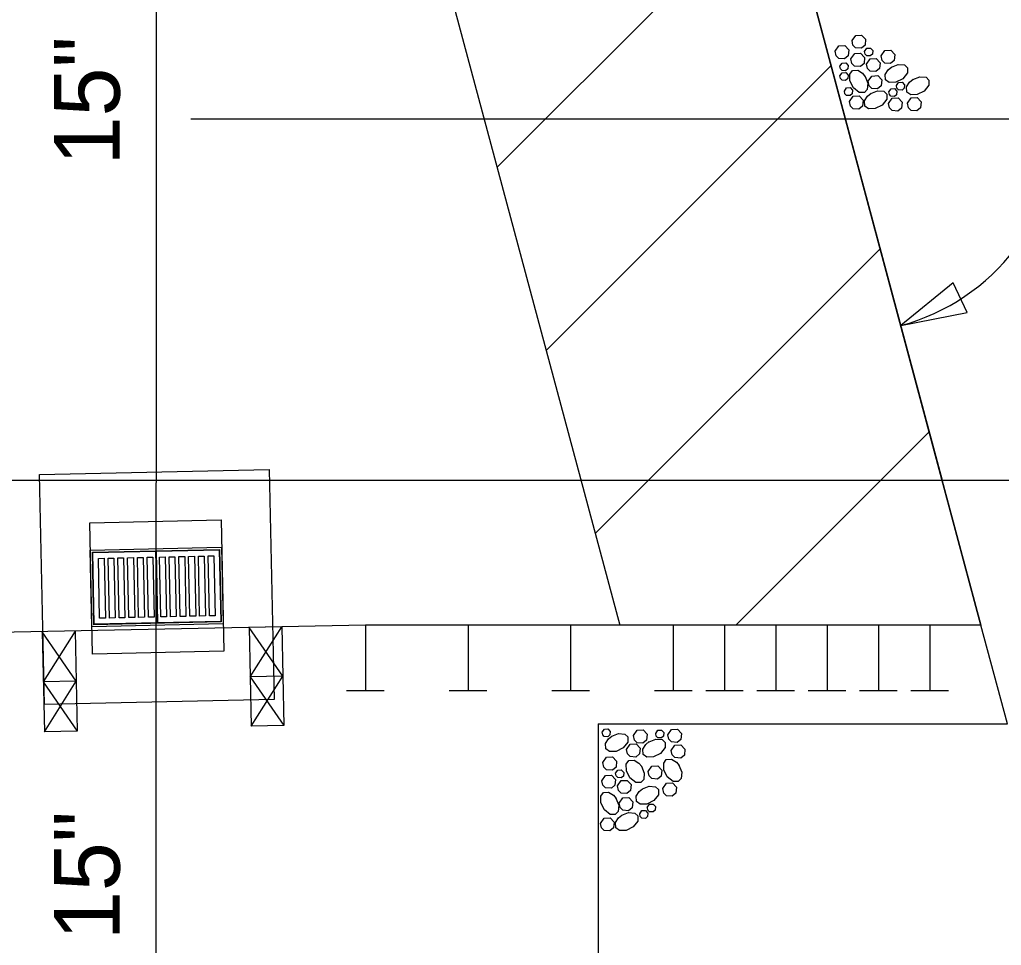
# Model space of a CAD drawing. Extents: x 471 to 2034, y -623 to 126.
# Drawn here: x 632.49 to 662.4, y -311.74 to -283.55 of the extents above; entities that cross this region are included whole.
import ezdxf

# ---------------------------------------------------------------- set-up
doc = ezdxf.new("R2010")
doc.units = 0
for name, color, linetype in [('Auto Dimensioning', 7, 'Continuous'), ('Default', 7, 'Continuous'), ('Mis Object Lines', 7, 'Continuous'), ('Miscellaneous Lines CELL', 7, 'Continuous'), ('Prop EOT', 7, 'Continuous'), ('Prop Horizontal Alignment', 7, 'Continuous'), ('Sub End Bent Cap Lines CELL', 7, 'Continuous'), ('Sup Concrete Girder Lines', 7, 'Continuous'), ('Text', 7, 'Continuous')]:
    doc.layers.add(name, color=color, linetype=linetype)

# ---------------------------------------------------------------- blocks, each defined once
blk = doc.blocks.new('AH')
at = {"layer": 'Sub End Bent Cap Lines CELL'}
blk.add_lwpolyline([(0, 0), (-1.25, 0.312), (-1.25, -0.312)], close=True, dxfattribs=at)

msp = doc.modelspace()

# ---------------------------------------------------------------- linework, layer by layer
at = {"layer": 'Auto Dimensioning'}
msp.add_arc((657.644, -286.575), 6.513, 285, 360, dxfattribs=at)
at = {"layer": 'Default'}
for p, q in [((661.775, -301.992), (653.513, -271.159)), ((654.697, -275.575), (660.592, -297.575)), ((636.644, -299.662), (636.642, -314.576)), ((636.644, -299.662), (636.644, -299.662)), ((636.669, -300.828), (636.669, -300.828)), ((638.669, -300.785), (638.669, -300.785)), ((634.67, -300.871), (634.67, -300.871)), ((643.025, -301.992), (596.283, -302.927)), ((636.694, -301.995), (636.694, -301.995)), ((643.025, -301.992), (643.025, -303.992)), ((661.775, -301.992), (643.025, -301.992)), ((646.15, -301.992), (646.15, -303.992)), ((649.275, -301.992), (649.275, -303.992)), ((652.4, -301.992), (652.4, -303.992)), ((653.963, -301.992), (653.963, -303.992)), ((655.525, -301.992), (655.525, -303.992)), ((657.088, -301.992), (657.088, -303.992)), ((658.65, -301.992), (658.65, -303.992)), ((660.213, -301.992), (660.213, -303.992)), ((633.183, -302.189), (633.244, -305.241)), ((634.213, -303.695), (633.183, -302.189)), ((634.183, -302.169), (633.213, -303.715)), ((634.183, -302.169), (634.244, -305.221)), ((640.483, -302.043), (639.483, -302.063)), ((639.483, -302.063), (639.543, -305.062)), ((639.483, -302.063), (639.513, -303.563)), ((640.513, -303.543), (639.483, -302.063)), ((639.513, -303.563), (640.483, -302.043)), ((640.483, -302.043), (640.543, -305.042)), ((634.213, -303.695), (633.213, -303.715)), ((633.213, -303.715), (634.244, -305.221)), ((633.244, -305.241), (634.213, -303.695)), ((640.513, -303.543), (639.513, -303.563)), ((639.513, -303.563), (640.543, -305.042)), ((639.543, -305.062), (640.513, -303.543)), ((643.598, -303.992), (642.452, -303.992)), ((646.723, -303.992), (645.577, -303.992)), ((649.848, -303.992), (648.702, -303.992)), ((652.973, -303.992), (651.827, -303.992)), ((654.535, -303.992), (653.39, -303.992)), ((656.098, -303.992), (654.952, -303.992)), ((657.66, -303.992), (656.515, -303.992)), ((659.223, -303.992), (658.077, -303.992)), ((660.785, -303.992), (659.64, -303.992)), ((634.244, -305.221), (633.244, -305.241)), ((640.543, -305.042), (639.543, -305.062))]:
    msp.add_line(p, q, dxfattribs=at)
for points in [[(633.095, -297.404), (640.093, -297.254), (640.243, -304.252), (633.245, -304.402)], [(634.627, -298.872), (638.626, -298.786), (638.712, -302.785), (634.712, -302.871)]]:
    msp.add_lwpolyline(points, close=True, dxfattribs=at)
for points in [[(634.645, -299.705), (638.644, -299.619), (638.694, -301.952), (634.695, -302.037), (634.645, -299.705)], [(634.708, -299.766), (638.583, -299.683), (638.63, -301.891), (634.756, -301.974), (634.708, -299.766)], [(634.719, -299.776), (636.635, -299.735), (636.682, -301.922), (634.766, -301.963), (634.719, -299.776)], [(635.186, -299.948), (635.364, -299.945), (635.403, -301.767), (635.226, -301.771), (635.186, -299.948)], [(635.483, -299.942), (635.66, -299.938), (635.699, -301.761), (635.522, -301.764), (635.483, -299.942)], [(635.78, -299.936), (635.957, -299.932), (635.996, -301.754), (635.819, -301.758), (635.78, -299.936)], [(636.077, -299.929), (636.254, -299.925), (636.293, -301.748), (636.116, -301.752), (636.077, -299.929)], [(636.374, -299.923), (636.551, -299.919), (636.59, -301.742), (636.413, -301.745), (636.374, -299.923)], [(636.656, -299.734), (638.572, -299.693), (638.619, -301.88), (636.703, -301.921), (636.656, -299.734)], [(636.749, -299.915), (636.926, -299.911), (636.965, -301.734), (636.788, -301.737), (636.749, -299.915)], [(637.045, -299.908), (637.222, -299.905), (637.261, -301.727), (637.084, -301.731), (637.045, -299.908)], [(637.342, -299.902), (637.519, -299.898), (637.558, -301.721), (637.381, -301.725), (637.342, -299.902)], [(637.639, -299.896), (637.816, -299.892), (637.855, -301.714), (637.678, -301.718), (637.639, -299.896)], [(637.936, -299.889), (638.113, -299.886), (638.152, -301.708), (637.975, -301.712), (637.936, -299.889)], [(638.232, -299.883), (638.41, -299.879), (638.449, -301.702), (638.272, -301.705), (638.232, -299.883)], [(634.89, -299.955), (635.067, -299.951), (635.106, -301.773), (634.929, -301.777), (634.89, -299.955)]]:
    msp.add_lwpolyline(points, dxfattribs=at)
at = {"layer": 'Mis Object Lines'}
for p, q in [((642.513, -271.159), (650.775, -301.992)), ((647.038, -288.046), (655.714, -279.371)), ((648.533, -293.623), (657.208, -284.948)), ((650.027, -299.2), (658.702, -290.525)), ((654.306, -301.992), (660.197, -296.101)), ((661.775, -301.992), (650.775, -301.992))]:
    msp.add_line(p, q, dxfattribs=at)
msp.add_lwpolyline([(642.513, -271.159), (653.513, -271.159), (661.775, -301.992)], dxfattribs=at)
at = {"layer": 'Miscellaneous Lines CELL'}
for points in [[(657.847, -284.191), (657.959, -284.031), (658.138, -284.021), (658.263, -284.15), (658.245, -284.331), (658.134, -284.423), (657.958, -284.41), (657.874, -284.329), (657.847, -284.191)], [(657.333, -284.512), (657.445, -284.352), (657.624, -284.342), (657.748, -284.471), (657.73, -284.652), (657.62, -284.743), (657.443, -284.731), (657.36, -284.65), (657.333, -284.512)], [(657.816, -284.744), (657.928, -284.585), (658.107, -284.575), (658.231, -284.704), (658.213, -284.884), (658.103, -284.976), (657.926, -284.963), (657.843, -284.883), (657.816, -284.744)], [(658.232, -284.517), (658.3, -284.422), (658.407, -284.416), (658.482, -284.493), (658.471, -284.601), (658.404, -284.657), (658.298, -284.649), (658.249, -284.601), (658.232, -284.517)], [(658.735, -284.655), (658.847, -284.495), (659.026, -284.485), (659.15, -284.614), (659.132, -284.795), (659.022, -284.887), (658.845, -284.874), (658.762, -284.793), (658.735, -284.655)], [(657.48, -284.968), (657.547, -284.872), (657.654, -284.866), (657.729, -284.944), (657.718, -285.052), (657.652, -285.107), (657.546, -285.099), (657.496, -285.051), (657.48, -284.968)], [(658.289, -284.903), (658.401, -284.743), (658.58, -284.733), (658.705, -284.862), (658.687, -285.043), (658.576, -285.135), (658.4, -285.122), (658.317, -285.041), (658.29, -284.903)], [(659.048, -284.996), (659.258, -284.913), (659.45, -284.93), (659.542, -285.017), (659.539, -285.173), (659.4, -285.351), (659.185, -285.458), (658.983, -285.461), (658.869, -285.38), (658.859, -285.219), (658.951, -285.075), (659.057, -284.991)], [(657.48, -285.264), (657.547, -285.168), (657.654, -285.162), (657.729, -285.239), (657.718, -285.348), (657.652, -285.403), (657.546, -285.395), (657.496, -285.347), (657.48, -285.264)], [(658.244, -285.279), (658.327, -285.489), (658.311, -285.682), (658.224, -285.773), (658.067, -285.77), (657.89, -285.631), (657.782, -285.417), (657.779, -285.214), (657.86, -285.101), (658.021, -285.09), (658.165, -285.182), (658.249, -285.288)], [(658.339, -285.427), (658.451, -285.268), (658.63, -285.257), (658.755, -285.386), (658.737, -285.567), (658.626, -285.659), (658.449, -285.646), (658.366, -285.566), (658.339, -285.427)], [(659.699, -285.371), (659.908, -285.288), (660.101, -285.304), (660.192, -285.391), (660.189, -285.547), (660.05, -285.725), (659.836, -285.832), (659.634, -285.836), (659.52, -285.755), (659.509, -285.594), (659.601, -285.45), (659.707, -285.365)], [(659.199, -285.558), (659.266, -285.462), (659.374, -285.456), (659.448, -285.533), (659.438, -285.642), (659.371, -285.697), (659.265, -285.689), (659.215, -285.641), (659.199, -285.558)], [(657.615, -285.724), (657.682, -285.629), (657.79, -285.622), (657.864, -285.7), (657.853, -285.808), (657.787, -285.863), (657.681, -285.856), (657.631, -285.807), (657.615, -285.724)], [(657.771, -286.043), (657.884, -285.884), (658.062, -285.874), (658.187, -286.003), (658.169, -286.183), (658.058, -286.275), (657.882, -286.262), (657.799, -286.182), (657.772, -286.043)], [(658.418, -285.798), (658.627, -285.714), (658.82, -285.731), (658.911, -285.818), (658.908, -285.974), (658.769, -286.152), (658.555, -286.259), (658.353, -286.263), (658.239, -286.182), (658.228, -286.021), (658.32, -285.877), (658.426, -285.792)], [(658.968, -285.752), (659.035, -285.657), (659.143, -285.65), (659.217, -285.728), (659.206, -285.836), (659.14, -285.891), (659.034, -285.884), (658.984, -285.835), (658.968, -285.752)], [(658.96, -286.102), (659.073, -285.943), (659.251, -285.933), (659.376, -286.062), (659.358, -286.242), (659.247, -286.334), (659.071, -286.322), (658.988, -286.241), (658.961, -286.102)], [(659.539, -286.096), (659.651, -285.936), (659.83, -285.926), (659.954, -286.055), (659.936, -286.236), (659.825, -286.328), (659.649, -286.315), (659.566, -286.234), (659.539, -286.096)], [(650.236, -305.248), (650.303, -305.152), (650.41, -305.146), (650.485, -305.223), (650.474, -305.332), (650.408, -305.387), (650.302, -305.379), (650.252, -305.331), (650.236, -305.248)], [(650.526, -305.371), (650.736, -305.288), (650.928, -305.304), (651.02, -305.391), (651.017, -305.547), (650.878, -305.725), (650.663, -305.832), (650.461, -305.836), (650.347, -305.755), (650.337, -305.594), (650.429, -305.45), (650.535, -305.365)], [(651.19, -305.35), (651.302, -305.191), (651.481, -305.181), (651.605, -305.31), (651.587, -305.49), (651.477, -305.582), (651.3, -305.569), (651.217, -305.489), (651.19, -305.35)], [(651.87, -305.285), (651.937, -305.189), (652.045, -305.183), (652.119, -305.26), (652.108, -305.369), (652.042, -305.424), (651.936, -305.416), (651.886, -305.368), (651.87, -305.285)], [(652.237, -305.326), (652.349, -305.167), (652.528, -305.156), (652.652, -305.285), (652.634, -305.466), (652.524, -305.558), (652.347, -305.545), (652.264, -305.465), (652.237, -305.326)], [(650.979, -305.772), (651.091, -305.612), (651.27, -305.602), (651.395, -305.731), (651.377, -305.912), (651.266, -306.004), (651.089, -305.991), (651.006, -305.91), (650.979, -305.772)], [(651.665, -305.54), (651.875, -305.457), (652.067, -305.474), (652.159, -305.561), (652.156, -305.717), (652.017, -305.894), (651.802, -306.002), (651.6, -306.005), (651.486, -305.924), (651.475, -305.763), (651.568, -305.619), (651.673, -305.535)], [(652.343, -305.803), (652.455, -305.644), (652.634, -305.634), (652.758, -305.762), (652.74, -305.943), (652.629, -306.035), (652.453, -306.022), (652.37, -305.942), (652.343, -305.803)], [(650.261, -306.172), (650.373, -306.012), (650.552, -306.002), (650.676, -306.131), (650.658, -306.312), (650.548, -306.404), (650.371, -306.391), (650.288, -306.31), (650.261, -306.172)], [(651.437, -306.284), (651.52, -306.494), (651.503, -306.686), (651.416, -306.778), (651.26, -306.775), (651.083, -306.636), (650.975, -306.422), (650.972, -306.219), (651.053, -306.105), (651.214, -306.095), (651.358, -306.187), (651.442, -306.293)], [(652.576, -306.257), (652.659, -306.467), (652.642, -306.659), (652.555, -306.751), (652.399, -306.748), (652.221, -306.609), (652.114, -306.394), (652.111, -306.192), (652.191, -306.078), (652.353, -306.067), (652.497, -306.16), (652.581, -306.266)], [(650.646, -306.498), (650.713, -306.403), (650.82, -306.397), (650.895, -306.474), (650.884, -306.582), (650.818, -306.638), (650.712, -306.63), (650.662, -306.581), (650.646, -306.498)], [(651.638, -306.443), (651.75, -306.284), (651.929, -306.273), (652.054, -306.402), (652.036, -306.583), (651.925, -306.675), (651.748, -306.662), (651.665, -306.581), (651.638, -306.443)], [(650.229, -306.725), (650.341, -306.566), (650.52, -306.556), (650.645, -306.685), (650.627, -306.865), (650.516, -306.957), (650.34, -306.944), (650.256, -306.864), (650.229, -306.725)], [(650.703, -306.884), (650.815, -306.724), (650.994, -306.714), (651.118, -306.843), (651.1, -307.024), (650.99, -307.115), (650.813, -307.103), (650.73, -307.022), (650.703, -306.884)], [(652.087, -306.962), (652.199, -306.803), (652.378, -306.793), (652.502, -306.922), (652.484, -307.103), (652.373, -307.194), (652.197, -307.182), (652.114, -307.101), (652.087, -306.963)], [(650.657, -307.26), (650.741, -307.47), (650.724, -307.663), (650.637, -307.754), (650.481, -307.751), (650.303, -307.612), (650.196, -307.398), (650.192, -307.195), (650.273, -307.081), (650.434, -307.071), (650.578, -307.163), (650.663, -307.269)], [(651.462, -306.977), (651.671, -306.894), (651.864, -306.911), (651.955, -306.998), (651.952, -307.154), (651.813, -307.331), (651.599, -307.439), (651.397, -307.442), (651.283, -307.361), (651.272, -307.2), (651.364, -307.056), (651.47, -306.972)], [(650.753, -307.408), (650.865, -307.248), (651.044, -307.238), (651.168, -307.367), (651.15, -307.548), (651.039, -307.64), (650.863, -307.627), (650.78, -307.546), (650.753, -307.408)], [(650.831, -307.778), (651.041, -307.695), (651.233, -307.712), (651.325, -307.799), (651.322, -307.955), (651.183, -308.133), (650.968, -308.24), (650.766, -308.244), (650.652, -308.163), (650.641, -308.002), (650.734, -307.858), (650.839, -307.773)], [(651.381, -307.733), (651.449, -307.637), (651.556, -307.631), (651.63, -307.709), (651.62, -307.817), (651.553, -307.872), (651.447, -307.865), (651.398, -307.816), (651.381, -307.733)], [(651.612, -307.539), (651.68, -307.443), (651.787, -307.437), (651.862, -307.514), (651.851, -307.623), (651.785, -307.678), (651.679, -307.67), (651.629, -307.622), (651.613, -307.539)], [(650.185, -308.024), (650.297, -307.865), (650.476, -307.855), (650.6, -307.984), (650.582, -308.164), (650.472, -308.256), (650.295, -308.243), (650.212, -308.163), (650.185, -308.024)]]:
    msp.add_lwpolyline(points, dxfattribs=at)
at = {"layer": 'Prop EOT'}
msp.add_line((564.339, -297.575), (805.312, -297.575), dxfattribs=at)
at = {"layer": 'Prop Horizontal Alignment'}
msp.add_line((637.709, -286.575), (805.312, -286.575), dxfattribs=at)
msp.add_line((637.709, -286.575), (805.312, -286.575), dxfattribs=at)
at = {"layer": 'Sup Concrete Girder Lines'}
for p, q in [((636.647, -275.822), (636.642, -314.576)), ((636.644, -299.662), (636.644, -299.662)), ((636.669, -300.828), (636.669, -300.828)), ((638.669, -300.785), (638.669, -300.785)), ((634.67, -300.871), (634.67, -300.871)), ((636.694, -301.995), (636.694, -301.995)), ((662.579, -304.992), (661.775, -301.992)), ((650.111, -304.992), (650.111, -316.1)), ((650.111, -304.992), (662.579, -304.992))]:
    msp.add_line(p, q, dxfattribs=at)
for points in [[(633.095, -297.404), (640.093, -297.254), (640.243, -304.252), (633.245, -304.402)], [(634.627, -298.872), (638.626, -298.786), (638.712, -302.785), (634.712, -302.871)]]:
    msp.add_lwpolyline(points, close=True, dxfattribs=at)
for points in [[(634.645, -299.705), (638.644, -299.619), (638.694, -301.952), (634.695, -302.037), (634.645, -299.705)], [(634.708, -299.766), (638.583, -299.683), (638.63, -301.891), (634.756, -301.974), (634.708, -299.766)], [(634.719, -299.776), (636.635, -299.735), (636.682, -301.922), (634.766, -301.963), (634.719, -299.776)], [(635.186, -299.948), (635.364, -299.945), (635.403, -301.767), (635.226, -301.771), (635.186, -299.948)], [(635.483, -299.942), (635.66, -299.938), (635.699, -301.761), (635.522, -301.764), (635.483, -299.942)], [(635.78, -299.936), (635.957, -299.932), (635.996, -301.754), (635.819, -301.758), (635.78, -299.936)], [(636.077, -299.929), (636.254, -299.925), (636.293, -301.748), (636.116, -301.752), (636.077, -299.929)], [(636.374, -299.923), (636.551, -299.919), (636.59, -301.742), (636.413, -301.745), (636.374, -299.923)], [(636.656, -299.734), (638.572, -299.693), (638.619, -301.88), (636.703, -301.921), (636.656, -299.734)], [(636.749, -299.915), (636.926, -299.911), (636.965, -301.734), (636.788, -301.737), (636.749, -299.915)], [(637.045, -299.908), (637.222, -299.905), (637.261, -301.727), (637.084, -301.731), (637.045, -299.908)], [(637.342, -299.902), (637.519, -299.898), (637.558, -301.721), (637.381, -301.725), (637.342, -299.902)], [(637.639, -299.896), (637.816, -299.892), (637.855, -301.714), (637.678, -301.718), (637.639, -299.896)], [(637.936, -299.889), (638.113, -299.886), (638.152, -301.708), (637.975, -301.712), (637.936, -299.889)], [(638.232, -299.883), (638.41, -299.879), (638.449, -301.702), (638.272, -301.705), (638.232, -299.883)], [(634.89, -299.955), (635.067, -299.951), (635.106, -301.773), (634.929, -301.777), (634.89, -299.955)]]:
    msp.add_lwpolyline(points, dxfattribs=at)

# ---------------------------------------------------------------- block references
at = {"layer": 'Auto Dimensioning', "xscale": 1.6, "yscale": 1.5999999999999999, "rotation": -154.7315158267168}
msp.add_blockref('AH', (659.33, -292.866), dxfattribs=at)

# ---------------------------------------------------------------- texts
at = {"layer": 'Text'}
for p in [(635.541, -287.984), (635.541, -311.575)]:
    msp.add_text('15"', height=2, rotation=90, dxfattribs=at).set_placement(p)

doc.saveas('drawing.dxf')
